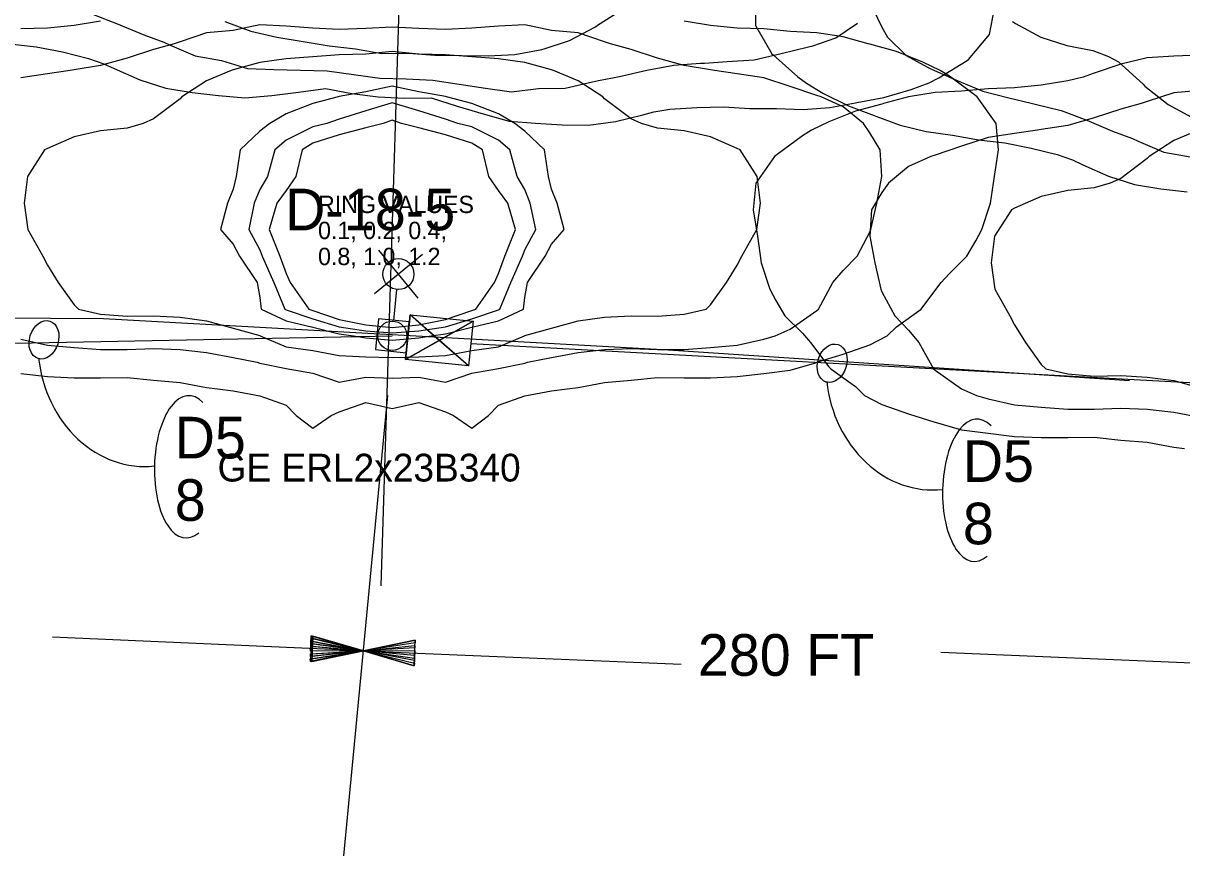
# Model space of a CAD drawing. Extents: x 1638506 to 1658005, y 834807 to 846788.
# Drawn here: x 1642635.4 to 1642969.6, y 842021.9 to 842261.9 of the extents above; entities that cross this region are included whole.
import ezdxf

# ---------------------------------------------------------------- set-up
doc = ezdxf.new("R2010")
doc.units = 0
for name, color, linetype in [('Default', 7, 'Continuous'), ('Old_Level_1', 7, 'Continuous'), ('Old_Level_2', 7, 'Continuous')]:
    doc.layers.add(name, color=color, linetype=linetype)

msp = doc.modelspace()

# ---------------------------------------------------------------- linework, layer by layer
at = {"layer": 'Default'}
for p, q in [((1642750.61, 842195.23), (1642736.75, 842183.92)), ((1642749.32, 842182.66), (1642738.01, 842196.49)), ((1642743.68, 842189.59), (1642743.68, 842189.59)), ((1642742.34, 842176.24), (1642743.23, 842185.14)), ((1642746.52, 842186.08), (1642746.52, 842186.08)), ((1642763.9, 842163.09), (1642747, 842177.8)), ((1642765.19, 842175.98), (1642745.71, 842164.91)), ((1642472.3, 842166.49), (1642741.9, 842171.8)), ((1642764.55, 842169.54), (1642998.17, 842156.92)), ((1642727.93, 842021.88), (1642740.63, 842154.55)), ((1642733.16, 842080.95), (1642643.92, 842084.89)), ((1642732.87, 842080.97), (1642825.15, 842077.1)), ((1642900.05, 842080.54), (1643012.72, 842075.81))]:
    msp.add_line(p, q, dxfattribs=at)
for points in [[(1642763.9, 842163.09), (1642745.71, 842164.91), (1642747, 842177.8), (1642765.19, 842175.98)], [(1642755.45, 842170.45), (1642747, 842177.8), (1642745.71, 842164.91)], [(1642745.91, 842166.92), (1642746.79, 842175.79), (1642737.89, 842176.68), (1642737.01, 842167.81)], [(1642755.45, 842170.45), (1642765.19, 842175.98), (1642763.9, 842163.09)]]:
    msp.add_lwpolyline(points, close=True, dxfattribs=at)
for points in [[(1642718.38, 842081.6), (1642718.41, 842082.34), (1642733.16, 842080.95), (1642718.44, 842083.03), (1642718.47, 842083.77), (1642733.16, 842080.95), (1642718.5, 842084.51), (1642718.54, 842085.25), (1642733.16, 842080.95), (1642718.26, 842077.9), (1642718.25, 842078.65), (1642733.16, 842080.95), (1642718.33, 842079.38), (1642718.31, 842080.12), (1642733.16, 842080.95), (1642718.34, 842080.86), (1642718.54, 842085.25), (1642718.26, 842077.9), (1642733.16, 842080.95), (1642718.54, 842085.25)], [(1642718.8, 842081.58), (1642718.84, 842082.32), (1642733.59, 842080.93), (1642718.87, 842083.01), (1642718.9, 842083.75), (1642733.59, 842080.93), (1642718.93, 842084.49), (1642718.96, 842085.23), (1642733.59, 842080.93), (1642718.69, 842077.89), (1642718.67, 842078.63), (1642733.59, 842080.93), (1642718.75, 842079.36), (1642718.74, 842080.11), (1642733.59, 842080.93), (1642718.77, 842080.84), (1642718.96, 842085.23), (1642718.69, 842077.89), (1642733.59, 842080.93), (1642718.96, 842085.23)], [(1642748.37, 842080.32), (1642748.34, 842079.58), (1642733.59, 842080.94), (1642748.31, 842078.89), (1642748.28, 842078.15), (1642733.59, 842080.94), (1642748.25, 842077.41), (1642748.22, 842076.67), (1642733.59, 842080.94), (1642748.48, 842084.02), (1642748.49, 842083.28), (1642733.59, 842080.94), (1642748.41, 842082.54), (1642748.43, 842081.8), (1642733.59, 842080.94), (1642748.4, 842081.06), (1642748.22, 842076.67), (1642748.48, 842084.02), (1642733.59, 842080.94), (1642748.22, 842076.67)], [(1642748.37, 842080.32), (1642748.34, 842079.58), (1642733.59, 842080.94), (1642748.31, 842078.89), (1642748.28, 842078.15), (1642733.59, 842080.94), (1642748.25, 842077.41), (1642748.22, 842076.67), (1642733.59, 842080.94), (1642748.48, 842084.02), (1642748.49, 842083.28), (1642733.59, 842080.94), (1642748.41, 842082.54), (1642748.43, 842081.8), (1642733.59, 842080.94), (1642748.4, 842081.06), (1642748.22, 842076.67), (1642748.48, 842084.02), (1642733.59, 842080.94), (1642748.22, 842076.67)]]:
    msp.add_lwpolyline(points, dxfattribs=at)
msp.add_circle((1642743.67, 842189.56), 4.47, dxfattribs=at)
for centre in [(1642641.45, 842170.62), (1642868.74, 842163.86)]:
    msp.add_ellipse(centre, major_axis=(1.72, 5.4), ratio=0.730797, dxfattribs=at)
for centre, major_axis, ratio, start_param, end_param in [((1642669.51, 842168.59), (-3.78, 34.34), 0.862742, 1.570796, 3.141593), ((1642896.8, 842161.83), (-3.78, 34.34), 0.862742, 1.570796, 3.141593), ((1642682.86, 842134.02), (-0.49, -20.52), 0.466223, 2.710831, 4.712389), ((1642910.15, 842127.26), (-0.49, -20.52), 0.466223, 2.710831, 4.712389), ((1642682.86, 842134.02), (-0.49, -20.52), 0.466223, 4.712389, 6.681485), ((1642910.15, 842127.26), (-0.49, -20.52), 0.466223, 4.712389, 6.681485)]:
    msp.add_ellipse(centre, major_axis=major_axis, ratio=ratio, start_param=start_param, end_param=end_param, dxfattribs=at)
at = {"layer": 'Old_Level_1'}
for points in [[(1642846.54, 842268.89), (1642846.61, 842261.2), (1642851.32, 842253.11)], [(1642631.62, 842255.97), (1642639.22, 842255.09), (1642646.77, 842253.64), (1642654.29, 842251.75), (1642658.67, 842250.22), (1642661.71, 842248.81), (1642669.1, 842245.55), (1642676.57, 842243.13), (1642684.14, 842241.92), (1642691.74, 842241.03), (1642699.37, 842240.36), (1642707.11, 842241.08), (1642714.87, 842241.99), (1642722.64, 842243.04), (1642730.19, 842241.61), (1642737.79, 842240.65), (1642745.43, 842240.28), (1642753.12, 842240.37), (1642760.59, 842237.99), (1642768.07, 842235.74), (1642775.57, 842233.7), (1642783.2, 842233.03), (1642790.84, 842232.59), (1642798.5, 842232.46), (1642806.28, 842233.54), (1642814.13, 842235.47), (1642817.36, 842236.34), (1642821.95, 842237.09), (1642829.67, 842237.64), (1642837.36, 842237.76), (1642845, 842237.3), (1642852.69, 842237.35), (1642860.34, 842237.04), (1642868.07, 842237.6), (1642875.43, 842238.94), (1642875.87, 842239.03), (1642883.67, 842240.45), (1642891.56, 842242.81), (1642896.76, 842244.75), (1642899.54, 842246.18), (1642907.65, 842251.17), (1642908.08, 842251.44), (1642914.13, 842258.59), (1642915.53, 842266.15)], [(1642655.4, 842264.5), (1642662.83, 842261.66), (1642670.24, 842258.53), (1642676.01, 842256.38), (1642677.67, 842255.65), (1642685.07, 842252.45), (1642692.63, 842251.11), (1642700.1, 842248.8), (1642707.76, 842248.51), (1642715.42, 842248.36), (1642723.08, 842248.13), (1642730.68, 842247.15), (1642738.26, 842246.09), (1642745.92, 842245.81), (1642753.57, 842245.46), (1642761.15, 842244.36), (1642768.73, 842243.18), (1642776.31, 842242.14), (1642784.08, 842243.11), (1642791.76, 842243.12), (1642799.6, 842244.98), (1642801.36, 842245.42), (1642807.41, 842246.53), (1642815.25, 842248.33), (1642823.06, 842249.83), (1642830.79, 842250.33), (1642831.9, 842250.42), (1642838.51, 842250.81), (1642846.23, 842251.36), (1642854.07, 842253.14), (1642861.92, 842255.06), (1642863.18, 842255.37), (1642869.82, 842257.66), (1642876.02, 842261.92)], [(1642693.61, 842262.35), (1642701.05, 842259.57), (1642708.57, 842257.84), (1642716.15, 842256.62), (1642723.72, 842255.38), (1642731.32, 842254.55), (1642738.88, 842253.15), (1642746.57, 842253.22), (1642754.2, 842252.71), (1642761.87, 842252.62), (1642769.54, 842252.5), (1642777.25, 842252.9), (1642785.06, 842254.35), (1642785.65, 842254.47), (1642792.96, 842256.86), (1642800.46, 842260.85), (1642801.03, 842261.36), (1642809.16, 842266.45)], [(1642880.53, 842265.91), (1642883.11, 842260.75), (1642884.72, 842257.87), (1642890.07, 842252.59), (1642896.21, 842249.18), (1642897.41, 842248.66), (1642904.8, 842245.4), (1642912.21, 842242.3), (1642919.73, 842240.41), (1642926.16, 842238.89), (1642927.25, 842238.6), (1642934.77, 842236.77), (1642942.2, 842233.93), (1642949.6, 842230.8), (1642955.37, 842228.65), (1642957.03, 842227.91), (1642964.43, 842224.72), (1642971.99, 842223.38)], [(1642657.75, 842262.46), (1642650.1, 842261.23), (1642642.45, 842260.45), (1642634.8, 842260.24)], [(1642882.62, 842225.35), (1642879.6, 842230.28), (1642877.75, 842233), (1642871.95, 842237.79), (1642865.54, 842240.65), (1642864.3, 842241.07), (1642856.65, 842243.67), (1642849, 842246.12), (1642841.35, 842247.34), (1642834.8, 842248.3), (1642833.7, 842248.49), (1642826.05, 842249.66), (1642818.4, 842251.84), (1642810.75, 842254.32), (1642804.82, 842255.95), (1642803.1, 842256.54), (1642795.45, 842259.08), (1642787.8, 842259.76), (1642780.15, 842261.4), (1642772.5, 842261.03), (1642764.85, 842260.51), (1642757.2, 842260.07), (1642749.55, 842260.39), (1642741.9, 842260.78), (1642734.25, 842260.39), (1642726.6, 842260.07), (1642718.95, 842260.51), (1642711.3, 842261.03), (1642703.65, 842261.4), (1642696, 842259.76), (1642688.35, 842259.08), (1642680.7, 842256.54), (1642678.98, 842255.95), (1642673.05, 842254.32), (1642665.4, 842251.84), (1642657.75, 842249.66), (1642650.1, 842248.49), (1642649, 842248.3), (1642642.45, 842247.34), (1642634.8, 842246.12)], [(1642910.6, 842240.65), (1642910.2, 842240.96), (1642902.55, 842246.63), (1642899.91, 842248.3), (1642894.9, 842250.69), (1642887.25, 842253.73), (1642879.6, 842255.82), (1642879.16, 842255.95), (1642871.95, 842257.92), (1642864.3, 842259.16), (1642856.65, 842259.51), (1642849, 842260.24), (1642841.35, 842260.45), (1642833.7, 842261.23), (1642826.05, 842262.46)], [(1642920.78, 842262.39), (1642921.6, 842261.85), (1642928.93, 842257.86), (1642936.4, 842255.48), (1642943.96, 842254.07), (1642948.44, 842252.29), (1642951.34, 842250.71), (1642958.46, 842244.29), (1642958.94, 842243.7), (1642965.63, 842238.46), (1642972.41, 842234.84)], [(1642842.22, 842225.35), (1642841.35, 842225.82), (1642833.7, 842229.16), (1642826.05, 842230.88), (1642818.4, 842231.63), (1642813.78, 842233), (1642810.75, 842234.32), (1642803.1, 842240.1), (1642802.57, 842240.65), (1642795.45, 842245.29), (1642788.38, 842248.3), (1642787.8, 842248.47), (1642780.15, 842250.6), (1642772.5, 842251.67), (1642764.85, 842252.22), (1642757.2, 842252.8), (1642749.55, 842252.96), (1642741.9, 842253.69), (1642734.25, 842252.96), (1642726.6, 842252.8), (1642718.95, 842252.22), (1642711.3, 842251.67), (1642703.65, 842250.6), (1642696, 842248.47), (1642695.42, 842248.3), (1642688.35, 842245.29), (1642681.22, 842240.65), (1642680.7, 842240.1), (1642673.05, 842234.32), (1642670.02, 842233), (1642665.4, 842231.63), (1642657.75, 842230.88), (1642650.1, 842229.16), (1642642.45, 842225.82), (1642641.58, 842225.35), (1642636.65, 842217.7), (1642635.73, 842210.05), (1642636.79, 842202.4), (1642641.09, 842194.75), (1642642.45, 842192.16), (1642645.55, 842187.1), (1642650.1, 842180.73), (1642651.44, 842179.45), (1642657.75, 842178.04), (1642665.4, 842177.41), (1642673.05, 842177.55), (1642680.7, 842177.12), (1642688.35, 842176.07), (1642696, 842174.02), (1642703.65, 842171.85), (1642703.78, 842171.8), (1642711.3, 842168.58), (1642718.95, 842167.58), (1642726.6, 842166.1), (1642734.25, 842165.69), (1642741.9, 842165.52), (1642749.55, 842165.69), (1642757.2, 842166.1), (1642764.85, 842167.58), (1642772.5, 842168.58), (1642780.02, 842171.8), (1642780.15, 842171.85), (1642787.8, 842174.02), (1642795.45, 842176.07), (1642803.1, 842177.12), (1642810.75, 842177.55), (1642818.4, 842177.41), (1642826.05, 842178.04), (1642832.36, 842179.45), (1642833.7, 842180.73), (1642838.25, 842187.1), (1642841.35, 842192.16), (1642842.71, 842194.75), (1642847.01, 842202.4), (1642848.07, 842210.05), (1642847.14, 842217.7), (1642842.22, 842225.35)], [(1642974.91, 842252.66), (1642967.26, 842252.43), (1642959.61, 842251.89), (1642951.96, 842250.13), (1642944.31, 842247.53), (1642941.16, 842246.38), (1642936.66, 842245.24), (1642929.01, 842244.02), (1642921.36, 842243.23), (1642913.71, 842243.02), (1642906.06, 842242.29), (1642898.41, 842241.94), (1642890.76, 842240.7), (1642883.55, 842238.73), (1642883.11, 842238.6), (1642875.46, 842236.51), (1642867.81, 842233.47), (1642862.8, 842231.08), (1642860.16, 842229.41), (1642852.51, 842223.74), (1642852.11, 842223.43), (1642846.71, 842215.78), (1642845.97, 842208.13), (1642847.2, 842200.48), (1642848.26, 842192.83), (1642850.77, 842185.18), (1642852.51, 842181.96), (1642855.12, 842177.53), (1642860.16, 842172.55), (1642862.52, 842169.88), (1642867.81, 842162.87), (1642868.32, 842162.23), (1642875.46, 842157.14), (1642878.07, 842154.58), (1642883.11, 842151.96), (1642890.76, 842149.25), (1642898.36, 842146.93), (1642898.41, 842146.92), (1642906.06, 842144.69), (1642913.71, 842143.72), (1642921.36, 842142.8), (1642929.01, 842142.46), (1642936.66, 842142.42), (1642944.31, 842142.57), (1642951.96, 842141.73), (1642959.61, 842141.08), (1642967.26, 842139.68), (1642970.39, 842139.28)], [(1642851.32, 842253.11), (1642851.69, 842252.77), (1642858.82, 842246.45), (1642861.3, 842244.56), (1642866.09, 842241.74), (1642873.44, 842238.05), (1642880.88, 842235.3), (1642881.3, 842235.13), (1642888.32, 842232.54), (1642895.83, 842230.64), (1642903.42, 842229.62), (1642910.98, 842228.23), (1642918.58, 842227.36), (1642926.14, 842225.91), (1642933.65, 842224.02), (1642938.04, 842222.49), (1642941.07, 842221.07), (1642948.47, 842217.81), (1642955.93, 842215.39), (1642963.51, 842214.19), (1642971.11, 842213.29)], [(1642789.42, 842210.05), (1642787.8, 842214.05), (1642786.89, 842217.7), (1642785.77, 842225.35), (1642780.15, 842230.8), (1642777.24, 842233), (1642772.5, 842235.78), (1642764.85, 842238.74), (1642757.53, 842240.65), (1642757.2, 842240.72), (1642749.55, 842242.08), (1642741.9, 842243.79), (1642734.25, 842242.08), (1642726.6, 842240.72), (1642726.27, 842240.65), (1642718.95, 842238.74), (1642711.3, 842235.78), (1642706.56, 842233), (1642703.65, 842230.8), (1642698.03, 842225.35), (1642696.91, 842217.7), (1642696, 842214.04), (1642694.38, 842210.05), (1642692.37, 842202.4), (1642696, 842198.23), (1642697.87, 842194.75), (1642702.9, 842187.1), (1642703.65, 842182.8), (1642704.09, 842179.45), (1642711.3, 842176.09), (1642718.95, 842174.23), (1642726.6, 842172.31), (1642730.66, 842171.8), (1642734.25, 842171.21), (1642741.9, 842170.53), (1642749.55, 842171.21), (1642753.14, 842171.8), (1642757.2, 842172.31), (1642764.85, 842174.23), (1642772.5, 842176.09), (1642779.71, 842179.45), (1642780.15, 842182.8), (1642780.9, 842187.1), (1642785.93, 842194.75), (1642787.8, 842198.23), (1642791.43, 842202.4), (1642789.42, 842210.05)], [(1642634.8, 842160.94), (1642642.45, 842160.02), (1642650.1, 842159.68), (1642657.75, 842159.64), (1642665.4, 842159.79), (1642673.05, 842158.95), (1642680.7, 842158.3), (1642688.35, 842156.9), (1642691.48, 842156.5), (1642696, 842155.87), (1642703.65, 842154.48), (1642711.3, 842151.82), (1642714.19, 842148.85), (1642718.95, 842145.13), (1642724.28, 842148.85), (1642726.6, 842149.91), (1642734.25, 842152.51), (1642741.9, 842150.82), (1642749.55, 842152.51), (1642757.2, 842149.91), (1642759.52, 842148.85), (1642764.85, 842145.13), (1642769.61, 842148.85), (1642772.5, 842151.82), (1642780.15, 842154.48), (1642787.8, 842155.87), (1642792.32, 842156.5), (1642795.45, 842156.9), (1642803.1, 842158.3), (1642810.75, 842158.95), (1642818.4, 842159.79), (1642826.05, 842159.64), (1642833.7, 842159.68), (1642841.35, 842160.02), (1642849, 842160.94), (1642856.65, 842161.9), (1642864.3, 842164.13), (1642864.35, 842164.15), (1642871.95, 842166.47), (1642879.6, 842169.17), (1642884.64, 842171.8), (1642887.25, 842174.36), (1642894.39, 842179.45), (1642894.9, 842180.09), (1642900.19, 842187.1), (1642902.55, 842189.77), (1642907.59, 842194.75), (1642910.2, 842199.18), (1642911.94, 842202.4), (1642914.45, 842210.05), (1642915.51, 842217.7), (1642916.74, 842225.35), (1642916, 842233), (1642910.6, 842240.65)], [(1642974.91, 842242.54), (1642967.26, 842241.86), (1642959.61, 842239.32), (1642957.9, 842238.73), (1642951.96, 842237.1), (1642944.31, 842234.62), (1642936.66, 842232.44), (1642929.01, 842231.27), (1642927.91, 842231.08), (1642921.36, 842230.12), (1642913.71, 842228.9), (1642906.06, 842226.45), (1642898.41, 842223.85), (1642897.18, 842223.43), (1642890.76, 842220.57), (1642884.96, 842215.78), (1642883.11, 842213.06), (1642880.09, 842208.13), (1642879.62, 842200.48), (1642881.06, 842192.83), (1642882.77, 842185.18), (1642883.11, 842184.48), (1642886.79, 842177.53), (1642890.76, 842173.4), (1642893.75, 842169.88), (1642897.95, 842162.23), (1642898.41, 842161.87), (1642906.06, 842156.49), (1642910.39, 842154.58), (1642913.71, 842153.57), (1642921.36, 842151.85), (1642929.01, 842151.21), (1642936.66, 842150.66), (1642944.31, 842150.65), (1642951.96, 842150.94), (1642959.61, 842150.64), (1642967.26, 842149.76), (1642974.91, 842148.34)], [(1642781.69, 842210.05), (1642780.15, 842213.92), (1642777.94, 842217.7), (1642775.78, 842225.35), (1642772.5, 842228.13), (1642764.85, 842232.03), (1642760.81, 842233), (1642757.2, 842234.2), (1642749.55, 842236.59), (1642741.9, 842238.98), (1642734.25, 842236.59), (1642726.6, 842234.2), (1642722.98, 842233), (1642718.95, 842232.03), (1642711.3, 842228.13), (1642708.01, 842225.35), (1642705.86, 842217.7), (1642703.65, 842213.92), (1642702.1, 842210.05), (1642700.56, 842202.4), (1642703.65, 842196.55), (1642704.35, 842194.75), (1642707.73, 842187.1), (1642710.88, 842179.45), (1642711.3, 842179.26), (1642718.95, 842176.65), (1642726.6, 842174.41), (1642734.25, 842173.18), (1642741.9, 842172.59), (1642749.55, 842173.18), (1642757.2, 842174.41), (1642764.85, 842176.65), (1642772.5, 842179.26), (1642772.92, 842179.45), (1642776.07, 842187.1), (1642779.45, 842194.75), (1642780.15, 842196.55), (1642783.24, 842202.4), (1642781.69, 842210.05)], [(1642775.19, 842210.05), (1642772.5, 842213.7), (1642769.72, 842217.7), (1642767.89, 842225.35), (1642764.85, 842227.27), (1642757.2, 842229.73), (1642749.55, 842231.72), (1642744.53, 842233), (1642741.9, 842233.95), (1642739.27, 842233), (1642734.25, 842231.72), (1642726.6, 842229.73), (1642718.95, 842227.27), (1642715.91, 842225.35), (1642714.08, 842217.7), (1642711.3, 842213.7), (1642708.6, 842210.05), (1642706.36, 842202.4), (1642709.42, 842194.75), (1642711.3, 842189.77), (1642712.48, 842187.1), (1642717.83, 842179.45), (1642718.95, 842179.06), (1642726.6, 842176.5), (1642734.25, 842174.95), (1642741.9, 842174.18), (1642749.55, 842174.95), (1642757.2, 842176.5), (1642764.85, 842179.06), (1642765.97, 842179.45), (1642771.32, 842187.1), (1642772.5, 842189.77), (1642774.38, 842194.75), (1642777.44, 842202.4), (1642775.19, 842210.05)], [(1642974.34, 842231.08), (1642967.26, 842228.07), (1642960.14, 842223.43), (1642959.61, 842222.88), (1642951.96, 842217.11), (1642948.93, 842215.78), (1642944.31, 842214.41), (1642936.66, 842213.66), (1642929.01, 842211.94), (1642921.36, 842208.6), (1642920.49, 842208.13), (1642915.57, 842200.48), (1642914.64, 842192.83), (1642915.7, 842185.18), (1642920, 842177.53), (1642921.36, 842174.94), (1642924.46, 842169.88), (1642929.01, 842163.51), (1642930.35, 842162.23), (1642936.66, 842160.82), (1642944.31, 842160.19), (1642951.96, 842160.33), (1642959.61, 842159.9), (1642967.26, 842158.85), (1642974.91, 842156.8)], [(1642634.8, 842170.79), (1642642.45, 842169.07), (1642650.1, 842168.43), (1642657.75, 842167.88), (1642665.4, 842167.87), (1642673.05, 842168.16), (1642680.7, 842167.86), (1642688.35, 842166.98), (1642696, 842165.56), (1642702.94, 842164.15), (1642703.65, 842163.91), (1642711.3, 842162.37), (1642718.95, 842161.01), (1642726.6, 842158.44), (1642734.25, 842159.85), (1642741.9, 842159.55), (1642749.55, 842159.85), (1642757.2, 842158.44), (1642764.85, 842161.01), (1642772.5, 842162.37), (1642780.15, 842163.91), (1642780.86, 842164.15), (1642787.8, 842165.56), (1642795.45, 842166.98), (1642803.1, 842167.86), (1642810.75, 842168.16), (1642818.4, 842167.87), (1642826.05, 842167.88), (1642833.7, 842168.43), (1642841.35, 842169.07), (1642849, 842170.79), (1642852.32, 842171.8), (1642856.65, 842173.71), (1642864.3, 842179.09), (1642864.76, 842179.45), (1642868.97, 842187.1), (1642871.95, 842190.62), (1642875.92, 842194.75), (1642879.6, 842201.7), (1642879.94, 842202.4), (1642881.65, 842210.05), (1642883.1, 842217.7), (1642882.62, 842225.35)]]:
    msp.add_lwpolyline(points, dxfattribs=at)
msp.add_circle((1642741.9, 842171.8), 4.21, dxfattribs=at)
at = {"layer": 'Old_Level_2'}
for p, q in [((1642738.69, 842099.7), (1642749.71, 842452.88)), ((1642519.08, 842177.38), (1642658.6, 842176.81)), ((1642658.6, 842176.81), (1642821.55, 842167.69)), ((1642821.55, 842167.69), (1642954.5, 842158.86))]:
    msp.add_line(p, q, dxfattribs=at)

# ---------------------------------------------------------------- texts
at = {"layer": 'Default'}
for s, height, p in [('D-18-5', 12, (1642710.99, 842202.19)), ('D5', 12, (1642679.15, 842136.43)), ('D5', 11.995, (1642906.44, 842129.66)), ('8', 12, (1642679.15, 842118.43)), ('8', 12, (1642906.44, 842111.67)), ('280 FT', 12, (1642830.01, 842073.78))]:
    msp.add_text(s, height=height, dxfattribs=at).set_placement(p)
at = {"layer": 'Old_Level_1'}
for s, height, p in [('RING VALUES', 5, (1642720.48, 842207.16)), ('0.1, 0.2, 0.4,', 5, (1642720.48, 842199.66)), ('0.8, 1.0, 1.2', 5, (1642720.48, 842192.16)), ('GE ERL2x23B340', 8, (1642691.49, 842129.78))]:
    msp.add_text(s, height=height, dxfattribs=at).set_placement(p)

doc.saveas('drawing.dxf')
